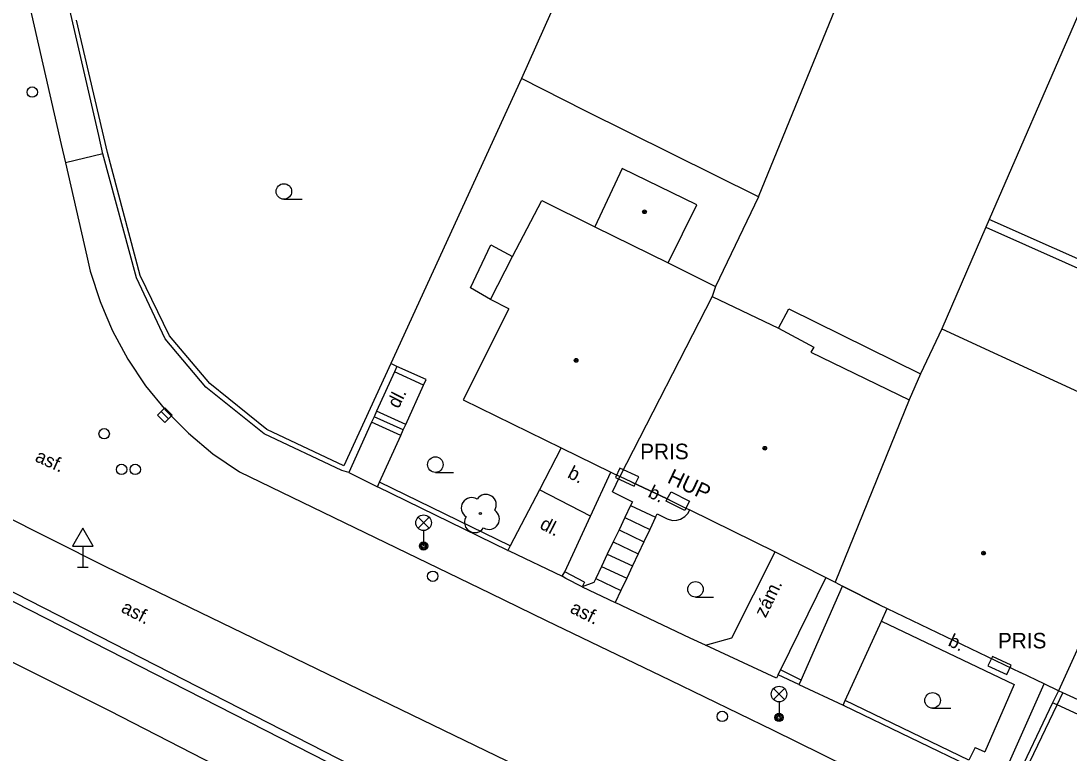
# Model space of a CAD drawing. Extents: x -600309 to -598967, y -1161267 to -1160292.
# Drawn here: x -600074.2 to -600023.6, y -1160842.3 to -1160807 of the extents above; entities that cross this region are included whole.
import ezdxf

# ---------------------------------------------------------------- set-up
doc = ezdxf.new("R2010")
doc.units = 0
for name, color, linetype in [('Level 10', 7, 'Continuous'), ('Level 11', 7, 'Continuous'), ('Level 14', 7, 'Continuous'), ('Level 22', 7, 'Continuous'), ('Level 24', 7, 'Continuous'), ('Level 27', 7, 'Continuous'), ('Level 28', 7, 'Continuous'), ('Level 31', 7, 'Continuous'), ('Level 33', 7, 'Continuous'), ('Level 34', 7, 'Continuous'), ('Level 36', 7, 'Continuous'), ('Level 39', 7, 'Continuous'), ('Level 40', 7, 'Continuous'), ('Level 41', 7, 'Continuous'), ('Level 5', 7, 'Continuous'), ('Level 51', 7, 'Continuous'), ('Level 54', 7, 'Continuous'), ('Level 6', 7, 'Continuous'), ('Level 7', 7, 'Continuous'), ('Level 8', 7, 'Continuous')]:
    doc.layers.add(name, color=color, linetype=linetype)

msp = doc.modelspace()

# ---------------------------------------------------------------- linework, layer by layer
at = {"layer": 'Level 10'}
for points in [[(-600040.57, -1160847.6599), (-600070.09, -1160833.36), (-600088.17, -1160824.28), (-600121.57, -1160807.3172), (-600123.12, -1160806.53), (-600128.62, -1160803.73), (-600139.56, -1160798.19)], [(-600075.33, -1160799.5), (-600072.24, -1160812.98)], [(-600072.24, -1160812.98), (-600072.04, -1160813.86)], [(-600072.04, -1160813.86), (-600071.0042, -1160818.3745), (-600070.84, -1160819.09)], [(-600070.84, -1160819.09), (-600070.37, -1160820.56), (-600070.0937, -1160821.2139), (-600069.77, -1160821.98), (-600069.03, -1160823.34), (-600068.17, -1160824.63), (-600067.19, -1160825.82), (-600066.1, -1160826.92), (-600064.92, -1160827.9099), (-600063.64, -1160828.78)], [(-600063.64, -1160828.78), (-600051.5409, -1160834.6369), (-600048.84, -1160835.95)], [(-600048.84, -1160835.95), (-600042.8628, -1160838.8377), (-600037.9, -1160841.24)], [(-600037.9, -1160841.24), (-600035.575, -1160842.3846), (-600034.17, -1160843.08)]]:
    msp.add_lwpolyline(points, dxfattribs=at)
at = {"layer": 'Level 11'}
for points in [[(-600070.23, -1160813.44), (-600072.04, -1160813.86)], [(-600051.53, -1160820.46), (-600052.5, -1160819.9), (-600051.51, -1160817.82), (-600050.4699, -1160818.38)], [(-600056.05, -1160823.69), (-600056.34, -1160823.55)], [(-600056.05, -1160823.69), (-600056.17, -1160823.96)], [(-600054.64, -1160824.32), (-600056.05, -1160823.69)], [(-600056.17, -1160823.96), (-600057.03, -1160825.85)], [(-600054.77, -1160824.6), (-600056.17, -1160823.96)], [(-600055.62, -1160826.49), (-600054.77, -1160824.6)], [(-600054.77, -1160824.6), (-600054.64, -1160824.32)], [(-600057.15, -1160826.12), (-600057.27, -1160826.39)], [(-600057.03, -1160825.85), (-600057.15, -1160826.12)], [(-600055.74, -1160826.76), (-600057.15, -1160826.12)], [(-600055.62, -1160826.49), (-600057.03, -1160825.85)], [(-600057.27, -1160826.39), (-600058.37, -1160828.81)], [(-600055.86, -1160827.03), (-600057.27, -1160826.39)], [(-600055.86, -1160827.03), (-600055.74, -1160826.76)], [(-600055.74, -1160826.76), (-600055.62, -1160826.49)], [(-600056.88, -1160829.28), (-600055.86, -1160827.03)], [(-600048.12, -1160827.62), (-600049.17, -1160829.64)], [(-600046.71, -1160830.92), (-600045.7199, -1160828.79)], [(-600045.65, -1160829.74), (-600045.29, -1160829)], [(-600049.17, -1160829.64), (-600050.58, -1160832.35)], [(-600046.71, -1160830.92), (-600049.17, -1160829.64)], [(-600045.65, -1160829.74), (-600044.68, -1160830.2199)], [(-600044.68, -1160830.2199), (-600044.77, -1160830.4099)], [(-600044.77, -1160830.4099), (-600045.05, -1160830.99)], [(-600044.77, -1160830.4099), (-600043.57, -1160830.9699)], [(-600043.57, -1160830.9699), (-600043.49, -1160830.8), (-600043.01, -1160831.04)], [(-600043.01, -1160831.04), (-600042.75, -1160831.12), (-600042.54, -1160831.11), (-600042.36, -1160831.06), (-600042.15, -1160830.94), (-600042.01, -1160830.79), (-600041.92, -1160830.62)], [(-600047.95, -1160833.6), (-600046.71, -1160830.92)], [(-600045.05, -1160830.99), (-600045.33, -1160831.58)], [(-600045.05, -1160830.99), (-600043.85, -1160831.56)], [(-600043.57, -1160830.9699), (-600043.85, -1160831.56)], [(-600045.33, -1160831.58), (-600045.61, -1160832.1599)], [(-600045.33, -1160831.58), (-600044.13, -1160832.15)], [(-600043.85, -1160831.56), (-600044.13, -1160832.15)], [(-600045.61, -1160832.1599), (-600045.9, -1160832.75)], [(-600045.61, -1160832.1599), (-600044.4099, -1160832.74)], [(-600044.13, -1160832.15), (-600044.4099, -1160832.74)], [(-600045.9, -1160832.75), (-600046.18, -1160833.34)], [(-600045.9, -1160832.75), (-600044.68, -1160833.32)], [(-600044.4099, -1160832.74), (-600044.68, -1160833.32)], [(-600039.88, -1160836.79), (-600037.79, -1160832.64)], [(-600046.18, -1160833.34), (-600046.45, -1160833.92)], [(-600046.18, -1160833.34), (-600044.96, -1160833.9099)], [(-600044.68, -1160833.32), (-600044.96, -1160833.9099)], [(-600035.36, -1160833.88), (-600037.54, -1160838.34)], [(-600046.45, -1160833.92), (-600046.55, -1160834.12), (-600047.11, -1160834.33)], [(-600046.45, -1160833.92), (-600045.24, -1160834.5)], [(-600044.96, -1160833.9099), (-600045.24, -1160834.5)], [(-600036.54, -1160838.83), (-600034.54, -1160834.29)], [(-600045.24, -1160834.5), (-600045.52, -1160835.09)], [(-600041.1599, -1160837.15), (-600041.892, -1160836.8042), (-600045.52, -1160835.09)], [(-600032.67, -1160835.99), (-600032.39, -1160835.37)], [(-600034.42, -1160839.81), (-600032.67, -1160835.99)], [(-600032.67, -1160835.99), (-600026.26, -1160839.04)], [(-600041.1599, -1160837.15), (-600039.88, -1160836.79)], [(-600037.65, -1160838.57), (-600037.73, -1160838.74), (-600041.1599, -1160837.15)], [(-600026.26, -1160839.04), (-600027.68, -1160842.29)], [(-600026.81, -1160843.5), (-600024.81, -1160839.01)], [(-600034.52, -1160840.04), (-600034.42, -1160839.81)], [(-600024.19, -1160840.03), (-600024.4099, -1160839.93)], [(-600019.65, -1160842.12), (-600024.19, -1160840.03)], [(-600028.15, -1160842.08), (-600028.45, -1160842.7)], [(-600028.15, -1160842.08), (-600027.68, -1160842.29)]]:
    msp.add_lwpolyline(points, dxfattribs=at)
at = {"layer": 'Level 14'}
msp.add_lwpolyline([(-600053.92, -1160848.53), (-600069.9099, -1160840.32), (-600081.6599, -1160834.46)], dxfattribs=at)
at = {"layer": 'Level 22'}
msp.add_circle((-600052.02, -1160830.79), 0.05, dxfattribs=at)
for centre, start, end in [((-600052.4419, -1160830.5216), 57.54, 237.54), ((-600051.7516, -1160830.3681), 327.54, 147.54), ((-600051.5981, -1160831.0584), 237.54, 57.54), ((-600052.2884, -1160831.2119), 147.54, 327.54)]:
    msp.add_arc(centre, 0.5, start, end, dxfattribs=at)
at = {"layer": 'Level 24'}
for points in [[(-600045.4988, -1160829.0545), (-600044.5931, -1160829.4784), (-600044.3812, -1160829.0255), (-600045.2869, -1160828.6016)], [(-600027.5287, -1160838.1369), (-600026.6211, -1160838.5569), (-600026.4111, -1160838.1031), (-600027.3187, -1160837.6831)]]:
    msp.add_lwpolyline(points, close=True, dxfattribs=at)
for points in [[(-600043.05, -1160830.2), (-600043, -1160830.09), (-600042.82, -1160829.75), (-600041.93, -1160830.2), (-600042.1, -1160830.53)], [(-600042.1, -1160830.53), (-600042.15, -1160830.64), (-600043.05, -1160830.2)]]:
    msp.add_lwpolyline(points, dxfattribs=at)
at = {"layer": 'Level 27'}
msp.add_line((-600067.4174, -1160825.8638), (-600067.0626, -1160826.2162), dxfattribs=at)
msp.add_lwpolyline([(-600067.5936, -1160826.0412), (-600067.2388, -1160826.3936), (-600066.8864, -1160826.0388), (-600067.2412, -1160825.6864)], close=True, dxfattribs=at)
at = {"layer": 'Level 28'}
for centre in [(-600070.17, -1160826.94), (-600069.33, -1160828.6599), (-600068.67, -1160828.6599), (-600054.32, -1160833.82), (-600040.35, -1160840.58)]:
    msp.add_circle(centre, 0.25, dxfattribs=at)
at = {"layer": 'Level 31'}
msp.add_circle((-600073.64, -1160810.45), 0.25, dxfattribs=at)
at = {"layer": 'Level 33'}
for p, q in [((-600055.025, -1160831.5), (-600054.495, -1160830.97)), ((-600055.025, -1160830.97), (-600054.495, -1160831.5)), ((-600054.76, -1160831.61), (-600054.76, -1160832.36)), ((-600037.875, -1160839.77), (-600037.345, -1160839.24)), ((-600037.875, -1160839.24), (-600037.345, -1160839.77)), ((-600037.61, -1160839.88), (-600037.61, -1160840.63))]:
    msp.add_line(p, q, dxfattribs=at)
for centre, radius in [((-600054.76, -1160831.235), 0.375), ((-600054.76, -1160832.36), 0.2), ((-600054.76, -1160832.36), 0.1445), ((-600054.76, -1160832.36), 0.0876), ((-600037.61, -1160839.505), 0.375), ((-600037.61, -1160840.63), 0.2), ((-600037.61, -1160840.63), 0.1445), ((-600037.61, -1160840.63), 0.0876)]:
    msp.add_circle(centre, radius, dxfattribs=at)
at = {"layer": 'Level 34'}
for p, q in [((-600071.2, -1160832.362), (-600071.2, -1160833.38)), ((-600071.45, -1160833.38), (-600070.95, -1160833.38))]:
    msp.add_line(p, q, dxfattribs=at)
msp.add_lwpolyline([(-600071.7, -1160832.362), (-600070.7, -1160832.362), (-600071.2, -1160831.496)], close=True, dxfattribs=at)
at = {"layer": 'Level 36'}
for p, q in [((-600061.5, -1160815.625), (-600060.625, -1160815.625)), ((-600054.19, -1160828.805), (-600053.315, -1160828.805)), ((-600041.64, -1160834.825), (-600040.765, -1160834.825)), ((-600030.2, -1160840.185), (-600029.325, -1160840.185))]:
    msp.add_line(p, q, dxfattribs=at)
for centre in [(-600061.5001, -1160815.2499), (-600054.1901, -1160828.4299), (-600041.6401, -1160834.4499), (-600030.2001, -1160839.8099)]:
    msp.add_circle(centre, 0.375, dxfattribs=at)
at = {"layer": 'Level 39'}
for centre, radius in [((-600044.1, -1160816.23), 0.09), ((-600044.1, -1160816.23), 0.0398), ((-600047.4, -1160823.4), 0.09), ((-600047.4, -1160823.4), 0.0398), ((-600038.3, -1160827.64), 0.09), ((-600038.3, -1160827.64), 0.0398), ((-600027.74, -1160832.7), 0.09), ((-600027.74, -1160832.7), 0.0398)]:
    msp.add_circle(centre, radius, dxfattribs=at)
at = {"layer": 'Level 5'}
for points in [[(-600045.18, -1160814.14), (-600046.5, -1160816.95)], [(-600041.58, -1160815.89), (-600045.18, -1160814.14)], [(-600050.4699, -1160818.38), (-600049.06, -1160815.68)], [(-600049.06, -1160815.68), (-600046.5, -1160816.95)], [(-600042.96, -1160818.7), (-600041.58, -1160815.89)], [(-600046.5, -1160816.95), (-600042.96, -1160818.7)], [(-600051.53, -1160820.46), (-600050.4699, -1160818.38)], [(-600042.96, -1160818.7), (-600040.67, -1160819.83)], [(-600040.67, -1160819.83), (-600040.84, -1160820.32)], [(-600050.64, -1160820.9099), (-600051.53, -1160820.46)], [(-600040.84, -1160820.32), (-600045.29, -1160829)], [(-600040.84, -1160820.32), (-600037.63, -1160821.85)], [(-600050.64, -1160820.9099), (-600052.85, -1160825.3)], [(-600037.63, -1160821.85), (-600035.93, -1160822.77)], [(-600029.76, -1160821.87), (-600030.78, -1160824.05)], [(-600029.76, -1160821.87), (-600018.59, -1160827.03)], [(-600035.93, -1160822.77), (-600036.07, -1160823)], [(-600036.07, -1160823), (-600031.33, -1160825.31)], [(-600030.78, -1160824.05), (-600031.33, -1160825.31)], [(-600052.85, -1160825.3), (-600048.12, -1160827.62)], [(-600031.33, -1160825.31), (-600034.9, -1160834.11)], [(-600048.12, -1160827.62), (-600045.7199, -1160828.79)], [(-600045.7199, -1160828.79), (-600045.29, -1160829)], [(-600044.7199, -1160829.27), (-600045.29, -1160829)], [(-600042.88, -1160830.15), (-600043, -1160830.09), (-600044.7199, -1160829.27)], [(-600019.59, -1160829.37), (-600024.13, -1160839.34)], [(-600042.88, -1160830.15), (-600042.1, -1160830.53)], [(-600042.1, -1160830.53), (-600041.92, -1160830.62)], [(-600041.92, -1160830.62), (-600037.79, -1160832.64)], [(-600037.79, -1160832.64), (-600035.36, -1160833.88)], [(-600035.36, -1160833.88), (-600034.9, -1160834.11)], [(-600034.9, -1160834.11), (-600034.54, -1160834.29)], [(-600034.54, -1160834.29), (-600032.77, -1160835.19)], [(-600032.77, -1160835.19), (-600032.39, -1160835.37)], [(-600032.39, -1160835.37), (-600025.96, -1160838.46)], [(-600024.81, -1160839.01), (-600025.96, -1160838.46)], [(-600024.13, -1160839.34), (-600024.81, -1160839.01)], [(-600023.9099, -1160839.44), (-600024.13, -1160839.34)], [(-600019.37, -1160841.52), (-600023.9099, -1160839.44)]]:
    msp.add_lwpolyline(points, dxfattribs=at)
at = {"layer": 'Level 51'}
for points in [[(-600011.07, -1160778.88), (-600027.47, -1160816.6), (-600027.63, -1160816.97)], [(-600039.85, -1160786.99), (-600050.03, -1160809.79)], [(-600038.6, -1160815.5), (-600028.9699, -1160791.92)], [(-600046.9699, -1160811.36), (-600050.03, -1160809.79)], [(-600038.6, -1160815.5), (-600046.9699, -1160811.36)], [(-600038.6, -1160815.5), (-600040.67, -1160819.83)], [(-600018.1599, -1160820.73), (-600027.47, -1160816.6)], [(-600027.63, -1160816.9699), (-600029.76, -1160821.87)]]:
    msp.add_lwpolyline(points, dxfattribs=at)
at = {"layer": 'Level 54'}
for points in [[(-600027.63, -1160816.97), (-600016.29, -1160822.03)], [(-600037.63, -1160821.85), (-600037.13, -1160820.9099)], [(-600037.13, -1160820.9099), (-600030.78, -1160824.05)]]:
    msp.add_lwpolyline(points, dxfattribs=at)
at = {"layer": 'Level 6'}
for points in [[(-600048.12, -1160827.62), (-600045.7199, -1160828.79)], [(-600044.7199, -1160829.27), (-600043, -1160830.09), (-600042.88, -1160830.15)], [(-600037.79, -1160832.64), (-600035.36, -1160833.88)], [(-600032.77, -1160835.19), (-600034.54, -1160834.29)], [(-600024.81, -1160839.01), (-600025.96, -1160838.46)]]:
    msp.add_lwpolyline(points, dxfattribs=at)
at = {"layer": 'Level 7'}
for points in [[(-600070.43, -1160812.55), (-600073.53, -1160799.08)], [(-600133.99, -1160809.4), (-600131.9099, -1160805.96), (-600102.93, -1160820.64), (-600102.12, -1160820.4699), (-600083.27, -1160830.08), (-600082.86, -1160830.8), (-600052.57, -1160846.27), (-600053.92, -1160848.53)], [(-600058.6, -1160828.49), (-600062.32, -1160826.73), (-600065.08, -1160824.51), (-600067.02, -1160822.2199), (-600068.43, -1160819.31), (-600070.01, -1160813.37), (-600071.51, -1160806.98)], [(-600050.03, -1160809.79), (-600056.34, -1160823.55), (-600058.6, -1160828.49)], [(-600070.23, -1160813.44), (-600070.43, -1160812.55)], [(-600058.37, -1160828.81), (-600058.71, -1160828.71), (-600062.45, -1160826.94), (-600065.26, -1160824.69), (-600067.23, -1160822.36), (-600068.61, -1160819.4099), (-600070.23, -1160813.44)], [(-600056.99, -1160829.51), (-600056.88, -1160829.28)], [(-600050.58, -1160832.35), (-600056.88, -1160829.28)], [(-600050.69, -1160832.57), (-600056.99, -1160829.51)], [(-600052.49, -1160846.71), (-600052.11, -1160846.08), (-600082.57, -1160830.5)], [(-600050.58, -1160832.35), (-600050.69, -1160832.57)], [(-600048.07, -1160833.82), (-600047.95, -1160833.6)], [(-600047.89, -1160833.92), (-600048.07, -1160833.82)], [(-600046.99, -1160834.11), (-600047.95, -1160833.6)], [(-600047.11, -1160834.33), (-600047.89, -1160833.92)], [(-600046.99, -1160834.11), (-600047.11, -1160834.33)], [(-600037.65, -1160838.57), (-600037.54, -1160838.34)], [(-600036.54, -1160838.83), (-600037.54, -1160838.34)], [(-600036.65, -1160839.05), (-600037.65, -1160838.57)], [(-600036.54, -1160838.83), (-600036.65, -1160839.05)], [(-600024.13, -1160839.34), (-600024.4099, -1160839.93)], [(-600024.19, -1160840.03), (-600023.9099, -1160839.44)], [(-600028.45, -1160842.7), (-600034.42, -1160839.81)], [(-600024.4099, -1160839.93), (-600026.27, -1160843.82)], [(-600028.06, -1160843.1599), (-600034.4687, -1160840.0648), (-600034.52, -1160840.04)], [(-600026.05, -1160843.92), (-600024.19, -1160840.03)]]:
    msp.add_lwpolyline(points, dxfattribs=at)
at = {"layer": 'Level 8'}
for points in [[(-600058.37, -1160828.81), (-600056.99, -1160829.51)], [(-600050.69, -1160832.57), (-600050.6312, -1160832.598), (-600048.07, -1160833.82)], [(-600047.11, -1160834.33), (-600045.52, -1160835.09)], [(-600036.65, -1160839.05), (-600034.52, -1160840.04)]]:
    msp.add_lwpolyline(points, dxfattribs=at)

# ---------------------------------------------------------------- texts
at = {"layer": 'Level 40'}
for s, rotation, p in [('dl.', 63.17, (-600055.9699, -1160825.76)), ('asf.', 335.85, (-600073.55, -1160828.25)), ('b.', 332.55, (-600047.86, -1160829.03)), ('b.', 333.78, (-600043.98, -1160829.9699)), ('dl.', 332.55, (-600049.2, -1160831.49)), ('zám.', 64, (-600038.26, -1160835.86)), ('asf.', 332.84, (-600069.4, -1160835.52)), ('asf.', 333.74, (-600047.74, -1160835.55)), ('b.', 334.51, (-600029.5, -1160837.15))]:
    msp.add_text(s, height=0.65, rotation=rotation, dxfattribs=at).set_placement(p)
at = {"layer": 'Level 41'}
for p in [(-600044.31, -1160828.17), (-600027.05, -1160837.3)]:
    msp.add_text('PRIS', height=0.75, dxfattribs=at).set_placement(p)
msp.add_text('HUP', height=0.75, rotation=334.65, dxfattribs=at).set_placement((-600043.05, -1160829.28))

doc.saveas('drawing.dxf')
